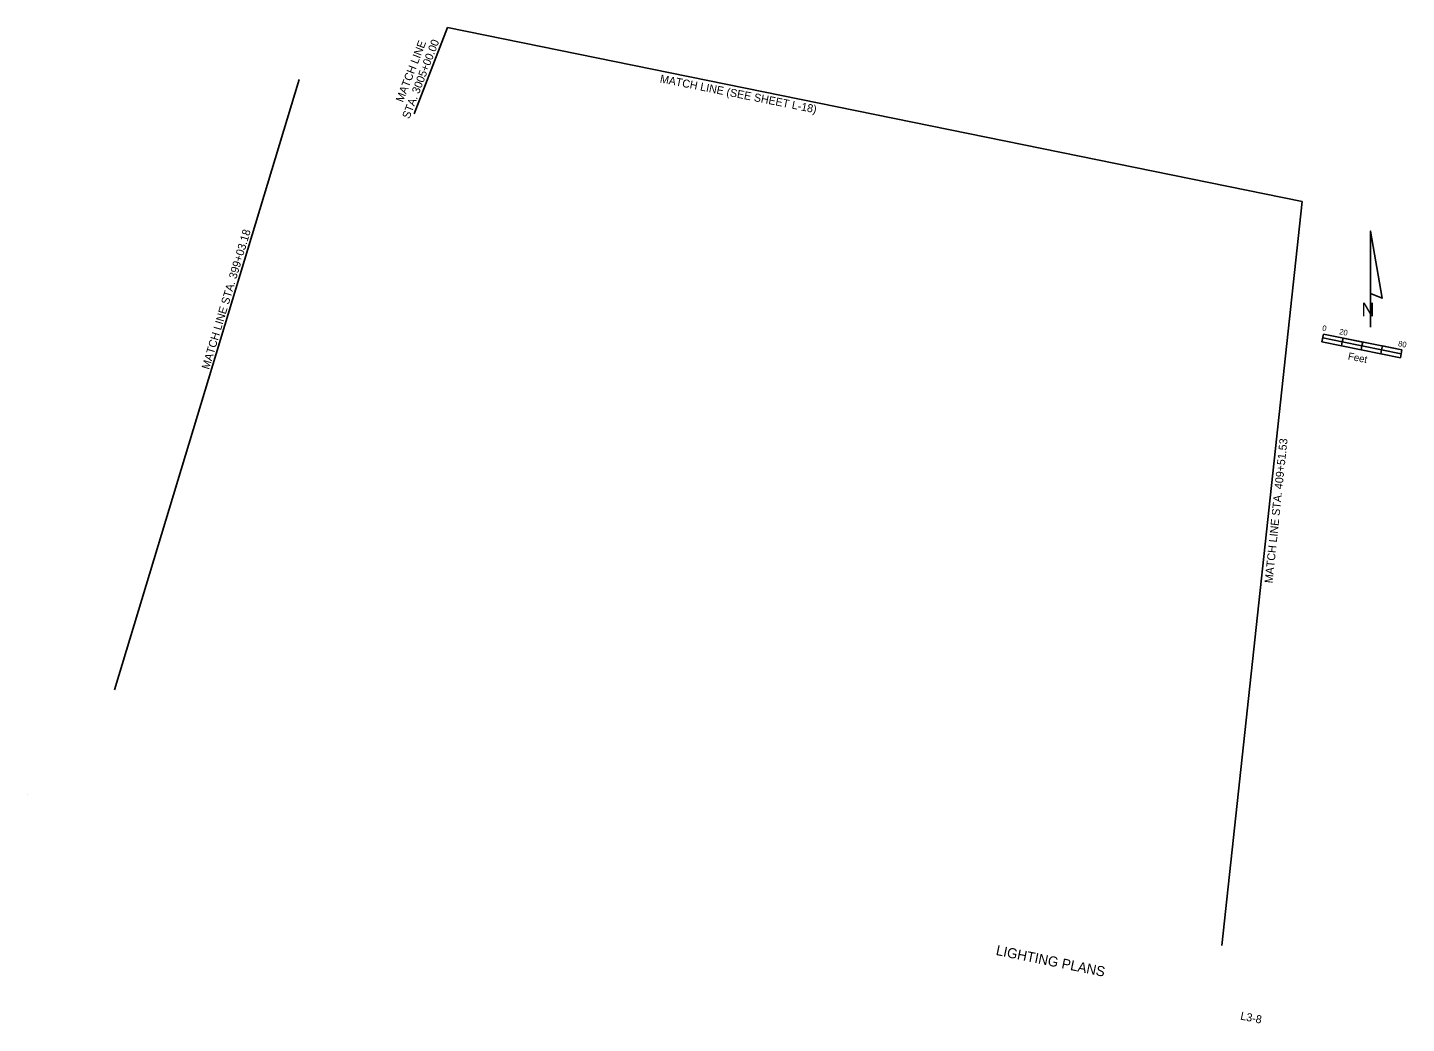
# Model space of a CAD drawing. Extents: x 918115 to 919494, y 636444 to 637440.
import ezdxf

# ---------------------------------------------------------------- set-up
doc = ezdxf.new("R2010")
doc.units = 0
for name, color, linetype in [('AdhocPoint_dp', 7, 'Continuous'), ('MatchLines_dp', 7, 'Continuous'), ('NorthArw_dp', 7, 'Continuous'), ('Scale_dp', 7, 'Continuous'), ('TextMisc', 7, 'Continuous'), ('TextShtNo', 7, 'Continuous')]:
    doc.layers.add(name, color=color, linetype=linetype)

msp = doc.modelspace()

# ---------------------------------------------------------------- linework, layer by layer
at = {"layer": 'AdhocPoint_dp'}
msp.add_line((918115.5, 636672.5), (918115.5, 636672.5), dxfattribs=at)
at = {"layer": 'MatchLines_dp'}
for p, q in [((918535, 637439.6), (918501.7, 637353.3)), ((919389.5, 637265.7), (918535, 637439.6)), ((918386.9, 637387.9), (918202.4, 636777.6)), ((919389.5, 637265.7), (919309.1, 636522))]:
    msp.add_line(p, q, dxfattribs=at)
at = {"layer": 'NorthArw_dp'}
msp.add_line((919457.7, 637140.2), (919457.7, 637236.2), dxfattribs=at)
msp.add_lwpolyline([(919457.7, 637173.8), (919457.7, 637236.2), (919469.3, 637169)], close=True, dxfattribs=at)
at = {"layer": 'Scale_dp'}
for p, q in [((919410.7, 637133.3), (919409.1, 637125.4)), ((919489.1, 637117.4), (919410.7, 637133.3)), ((919409.1, 637125.4), (919487.6, 637109.6)), ((919487.6, 637109.6), (919489.1, 637117.4))]:
    msp.add_line(p, q, dxfattribs=at)
for points in [[(919409.1, 637125.4), (919409.9, 637129.4), (919429.5, 637125.4), (919428.7, 637121.5)], [(919429.5, 637125.4), (919430.3, 637129.3), (919449.9, 637125.3), (919449.1, 637121.4)], [(919448.4, 637117.5), (919449.1, 637121.4), (919468.7, 637117.5), (919468, 637113.5)], [(919468.7, 637117.5), (919469.5, 637121.4), (919489.1, 637117.4), (919488.4, 637113.5)]]:
    msp.add_lwpolyline(points, close=True, dxfattribs=at)

# ---------------------------------------------------------------- texts
at = {"layer": 'MatchLines_dp'}
for s, rotation, p in [('MATCH LINE', 68.8833, (918490.6, 637364.4)), ('STA. 3005+00.00 ', 68.8833, (918497, 637347.9)), ('MATCH LINE (SEE SHEET L-18)', 348.7752, (918747, 637384.9)), ('MATCH LINE STA. 399+03.18', 73.3285, (918296.9, 637097.3)), ('MATCH LINE STA. 409+51.53', 84.0205, (919359.7, 636883.9))]:
    msp.add_text(s, height=8, rotation=rotation, dxfattribs=at).set_placement(p)
at = {"layer": 'NorthArw_dp'}
msp.add_text('N', height=13.4, dxfattribs=at).set_placement((919448.6, 637151.1))
at = {"layer": 'Scale_dp'}
for s, height, p in [('0', 5.6, (919409, 637136.7)), ('20', 5.6, (919426.1, 637133.2)), ('80', 5.6, (919484.9, 637121.3)), ('Feet', 7.2, (919434.7, 637108))]:
    msp.add_text(s, height=height, rotation=348.562, dxfattribs=at).set_placement(p)
at = {"layer": 'TextMisc'}
msp.add_text('        LIGHTING PLANS         ', height=10, rotation=348.562, dxfattribs=at).set_placement((919053.6, 636518.6))
at = {"layer": 'TextShtNo'}
msp.add_text(' L3-8 ', height=8, rotation=348.562, dxfattribs=at).set_placement((919324.2, 636448.7))

doc.saveas('drawing.dxf')
